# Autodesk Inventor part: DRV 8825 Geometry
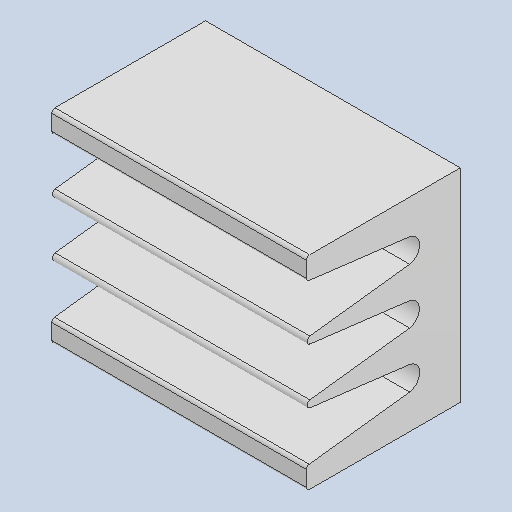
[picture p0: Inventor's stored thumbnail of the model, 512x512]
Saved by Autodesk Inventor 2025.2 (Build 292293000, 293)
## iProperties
Created: 2025-04
Part Number: DRV 8825 Geometry
Material: Generic
Description: PART-DRV 8825 Geometry-DESC
Document SubType Name: Modeling
Designer: BennF
Density: 1 g/cm^3
Appearance: Default
Author: BennF
Revision Number: NONE
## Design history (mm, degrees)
feature "Solid"
body "Solid1"
